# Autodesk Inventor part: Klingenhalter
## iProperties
Created: 2006-11
Part Number: Klingenhalter
Document SubType Name: Modeling
Designer: Kumpf
Manufacturer: Standard
Standards Organization: Custom
Author: Kumpf
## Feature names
1. Drehung1 [Revolution]
2. Rundung1 [Fillet]
3. Fase1 [Chamfer]
4. Bohrung1 [Hole]
5. Bohrung2 [Hole]
6. Fase2 [Chamfer]
